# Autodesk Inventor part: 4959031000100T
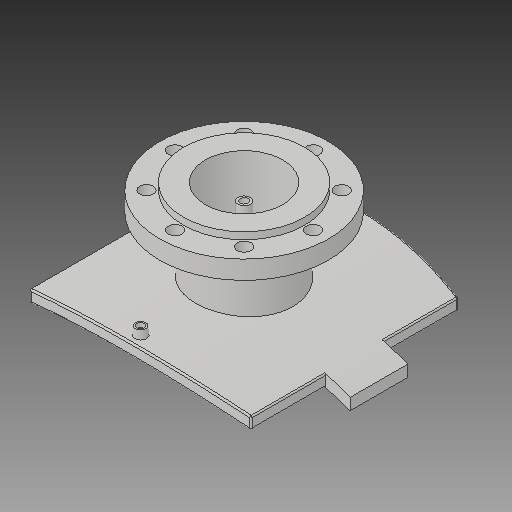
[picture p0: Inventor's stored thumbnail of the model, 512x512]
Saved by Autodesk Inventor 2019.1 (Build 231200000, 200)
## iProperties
Created: 2017-10
Part Number: 4959031000100T
Material: Generic
Description: PLASSON FLANGED BRANCH SADDLE 1000x100
Document SubType Name: Modeling
Designer: KIM
Mass: 2339.99 g
Surface Area: 3251.55 cm^2
Volume: 2339.99 cm^3
Density: 1 g/cm^3
Appearance: Default
Author: KIM
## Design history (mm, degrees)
derived "495904_495903.ipt"
feature "Solid1::495904_495903.ipt"
feature "Solid2::495904_495903.ipt"
tag "TaggingFeature1"
body "Solid1"
other parameters: "d1" = 15, "d2" = 288, "d4" = 0, "d6" = 75, "d7" = 0, "d12" = 525.6, "d13" = 14, "d14" = 135, "d16" = 5 deg, "d18" = 4, "d19" = 14, "d20" = 0, "d21" = 3, "d22" = 0, "d23" = 635, "d36" = 135, "d38" = 0, "d39" = 2, "d41" = 101, "d42" = 158, "d44" = 96, "d46" = 126.4, "d47" = 16, "d48" = 10.4, "d49" = 84, "d53" = 0, "d54" = 18, "d57" = 0, "d59" = 360 deg, "d61" = 24, "d63" = 0, "d67" = 15, "d70" = 0, "d71" = 2, "d_1" = 158, "x_" = 15, "D_" = 16, "DN_" = 101, "t_" = 24, "s_" = 18
